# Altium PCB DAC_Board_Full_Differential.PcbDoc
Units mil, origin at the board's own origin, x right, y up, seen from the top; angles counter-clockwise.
Board outline 2155 x 3965 mil, 2 copper layers (Top Layer, Bottom Layer); 107 components, 72 nets, 303 pads, 34 vias.
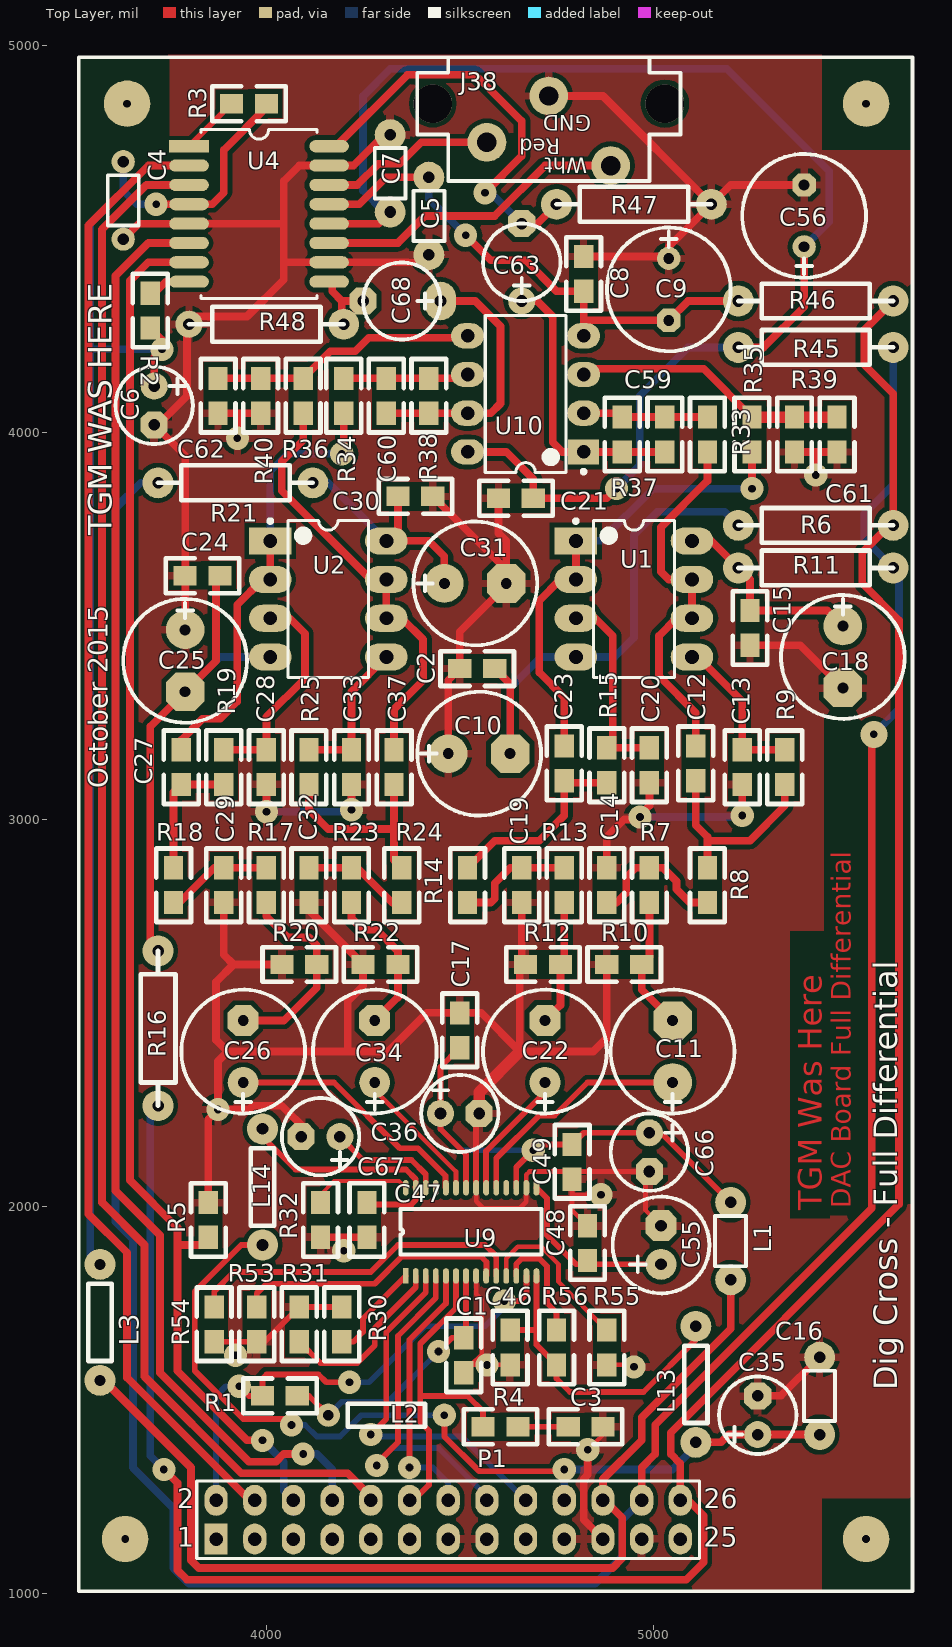
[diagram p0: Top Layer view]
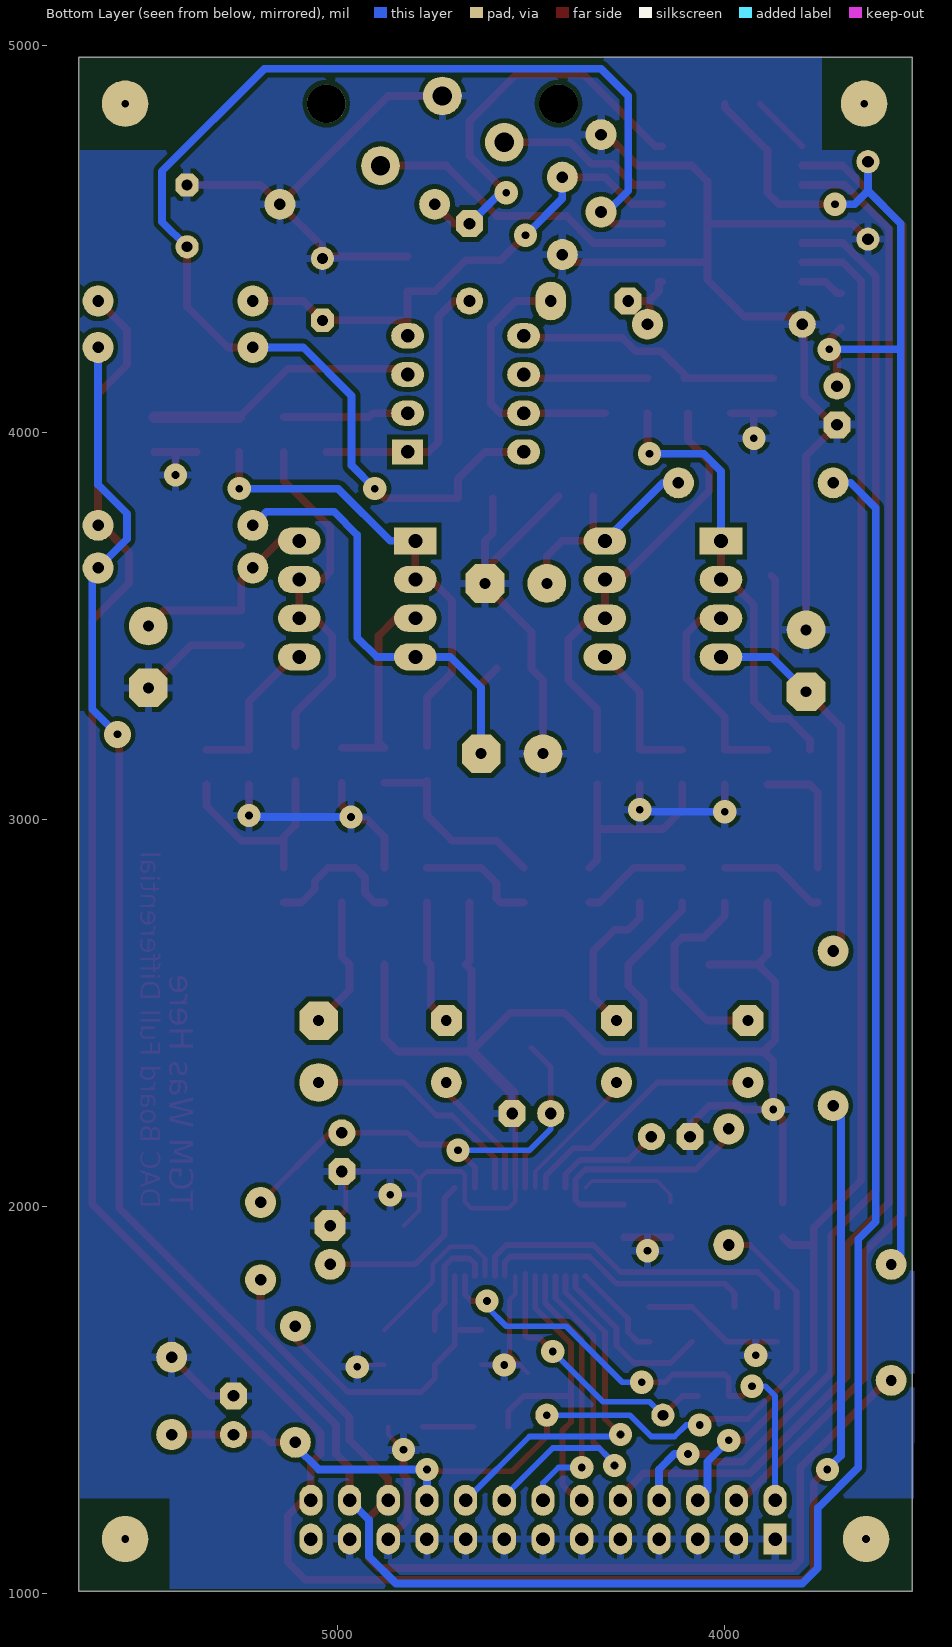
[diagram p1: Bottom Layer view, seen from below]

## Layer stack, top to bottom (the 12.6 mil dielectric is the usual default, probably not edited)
Top Layer: signal copper 1.4
Dielectric: core 12.6, FR-4, Dk 4.8
Bottom Layer: signal copper 1.4

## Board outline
3515,4970 5670,4970 5670,1005 3515,1005

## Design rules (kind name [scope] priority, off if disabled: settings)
Clearance Clearance_1 [(IsRegion)] p1: gap=12
Clearance [All] p2: gap=10
ComponentClearance [All] p1: gap=5 collisioncheckmode=3 verticalgap=10 showdistances=FALSE
HoleSize [All] p1: absolutevalues=TRUE maxlimit=255 minlimit=14 maxpercent=80.000 minpercent=20.000
MinimumSolderMaskSliver [All] p1: minsoldermaskwidth=5
PlaneConnect [All] p1: planeconnectstyle=Relief reliefexpansion=20 reliefentries=4 reliefconductorwidth=15 reliefairgap=10
PolygonConnect [All] p1: connectstyle=Relief reliefconductorwidth=20 reliefentries=4 polygonreliefangle="90 Angle"
RoutingVias [All] p1: holewidth=28 width=50 viastyle="Through Hole" minholewidth=28 minwidth=50 maxholewidth=28 maxwidth=50
SilkscreenOverComponentPads [All] p1: minsilkscreentomaskgap=10
SolderMaskExpansion [All] p1: expansion=4
Width [All] p1: maxlimit=255 minlimit=10 preferedwidth=10 minimp=50.000000 maximp=50.000000 favimp=50.000000
23 further rules are at their usual default settings.

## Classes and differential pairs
component class DAC_Board_Full_Differential: C2 C4 C5 C6 C7 C8 C9 C10 C11 C12 C13 C14 C15 C18 C19 C20 C21 C22 C23 C24 C25 C26 C27 C28 C29 C30 C31 C32 C33 C34 C37 C56 C59 C60 C61 C62 C63 C68 J38 L3 R2 R3 R5 R6 R7 R8 R9 R10 R11 R12 R13 R14 R15 R16 R17 R18 R19 R20 R21 R22 R23 R24 R25 R33 R34 R35 R36 R37 R38 R39 R40 R45 R46 R47 R48 R? U1 U2 U4 U10
component class DAC_Board_Full_Differential_Outputs: C1 C3 C16 C17 C35 C36 C46 C47 C48 C49 C55 C66 C67 L1 L2 L13 L14 P1 R1 R4 R30 R31 R32 R53 R54 R55 R56 U9

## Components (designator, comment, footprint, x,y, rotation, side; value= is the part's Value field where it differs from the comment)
C1 "100n" 0805 4510,1660 r270 top
C2 "100n" 0805 4590,3390 r180 top
C3 "27pF" 0805 4780,1430 r0 top
C4 "100n" AXIAL0.2#1 3630,4700 r270 top
C5 "100n" AXIAL0.2#2 4420,4660 r270 top
C6 "1uF" RB.1/.2 3710,4020 r90 top
C7 "100n" AXIAL0.2#2 4320,4570 r90 top
C8 "100n" 0805 4820,4455 r270 top
C9 "100uF" RB.16/.32-PTH#1 5040,4290 r90 top
C10 "100uF" RB.16/.32-PTH#2 4630,3170 r180 top
C11 "100uF" RB.16/.32-PTH#2 5050,2480 r270 top
C12 "1n8" 0805 5110,3190 r270 top
C13 "2n2" 0805 5230,3090 r90 top
C14 "15n" 0805 4880,2875 r270 top
C15 "100n" 0805 5250,3540 r270 top
C16 "100n" AXIAL0.2-PTH 5430,1410 r90 top
C17 "100n" 0805 4500,2410 r90 top
C18 "100uF" RB.16/.32-PTH#2 5490,3340 r90 top
C19 "15n" 0805 4660,2875 r270 top
C20 "2n2" 0805 4990,3095 r90 top
C21 "100n" 0805 4690,3830 r180 top
C22 "100uF" RB.16/.32-PTH#3 4720,2480 r270 top
C23 "1n8" 0805 4770,3190 r270 top
C24 "100n" 0805 3880,3630 r180 top
C25 "100uF" RB.16/.32-PTH#2 3790,3330 r90 top
C26 "100uF" RB.16/.32-PTH#3 3940,2480 r270 top
C27 "1n8" 0805 3780,3180 r270 top
C28 "2n2" 0805 4000,3090 r90 top
C29 "15n" 0805 3890,2785 r90 top
C30 "100n" 0805 4340,3835 r0 top
C31 "100uF" RB.16/.32-PTH#2 4620,3610 r180 top
C32 "15n" 0805 4110,2875 r270 top
C33 "2n2" 0805 4220,3090 r90 top
C34 "100uF" RB.16/.32-PTH#3 4280,2480 r270 top
C35 "10u" RB.1/.2 5270,1510 r270 top
C36 "10u" RB.1/.2 4550,2240 r180 top
C37 "1n8" 0805 4330,3180 r270 top
C46 "100n" 0805 4630,1680 r270 top
C47 "100n" 0805 4260,1920 r90 top
C48 "100n" 0805 4830,1950 r270 top
C49 "100n" 0805 4790,2070 r90 top
C55 "100uF" RB.1/.25-pth 5020,1850 r270 top
C56 "100uF" RB.16/.32-PTH#1 5390,4640 r270 top
C59 "1n" 0805 5030,4040 r270 top
C60 "1n" 0805 4310,4140 r270 top
C61 "1n" 0805 5475,3950 r90 top
C62 "1n" 0805 3875,4050 r90 top
C63 "22uF" RB.2/.2#1 4660,4340 r270 top
C66 "33uF" RB.1/.2 4990,2090 r90 top
C67 "3u3" RB.1/.2 4090,2180 r0 top
C68 "22uF" RB.2/.2#2 4450,4340 r0 top
J38 "Output Band 1" RCA-PCB-2IP 4570,4750 r180 top
L1 "bead" AXIAL0.2-pth 5200,2010 r270 top
L2 "bead" AXIAL0.3-pth#1 4460,1460 r180 top
L3 "bead" AXIAL0.3-pth#2 3570,1550 r90 top
L13 "bead" AXIAL0.3-pth#3 5110,1690 r270 top
L14 "bead" AXIAL0.3-pth#3 3990,1900 r90 top
P1 "Header 13X2" HDR2X13 3870,1140 r0 top
R1 "10K" 0805 3990,1510 r0 top
R2 "1K" 0805 3700,4360 r270 top
R3 "10K" 0805 3910,4850 r0 top
R4 "100R" 0805 4560,1430 r0 top
R5 "100K" 0805 3850,2010 r270 top
R6 "10" AXIAL0.4-pth 5220,3760 r0 top
R7 "196" 0805 4990,2875 r270 top
R8 "681" 0805 5140,2875 r270 top
R9 "464" 0805 5340,3180 r270 top
R10 "100k" 0805 4880,2625 r0 top
R11 "10" AXIAL0.4-pth 5220,3650 r0 top
R12 "100k" 0805 4760,2625 r180 top
R13 "196" 0805 4770,2875 r270 top
R14 "681" 0805 4520,2875 r270 top
R15 "464" 0805 4880,3185 r270 top
R16 "10" AXIAL0.4-pth 3720,2660 r270 top
R17 "196" 0805 4000,2875 r270 top
R18 "681" 0805 3760,2875 r270 top
R19 "464" 0805 3890,3180 r270 top
R20 "100k" 0805 4040,2625 r0 top
R21 "10" AXIAL0.4-pth 4120,3870 r180 top
R22 "100k" 0805 4340,2625 r180 top
R23 "196" 0805 4220,2875 r270 top
R24 "681" 0805 4350,2875 r270 top
R25 "464" 0805 4110,3180 r270 top
R30 "1K" 0805 4195,1740 r270 top
R31 "1K" 0805 4085,1740 r270 top
R32 "1K" 0805 4140,1920 r90 top
R33 "620" 0805 5140,3950 r90 top
R34 "620" 0805 4200,4050 r90 top
R35 "620" 0805 5255,3950 r90 top
R36 "620" 0805 4095,4050 r90 top
R37 "560" 0805 4920,4040 r270 top
R38 "560" 0805 4420,4140 r270 top
R39 "560" 0805 5365,4040 r270 top
R40 "560" 0805 3985,4140 r270 top
R45 "10" AXIAL0.4-PTH#1 5220,4220 r0 top
R46 "10" AXIAL0.4-PTH#1 5220,4340 r0 top
R47 "10k" AXIAL0.4-PTH#1 5150,4590 r180 top
R48 "10k" AXIAL0.4-PTH#2 4200,4280 r180 top
R53 "10K" 0805 3975,1650 r90 top
R54 "10K" 0805 3865,1650 r90 top
R55 "10K" 0805 4880,1590 r90 top
R56 "10K" 0805 4750,1590 r90 top
U1 "LM4562" DIP-8#1 4950,3570 r0 top
U2 "LM4562" DIP-8#1 4160,3570 r0 top
U4 "PGA2320" SO16W 3800,4740 r0 top
U9 "CS4398" TSSOP28 4360,1820 r90 top
U10 "LM4562" DIP-8#2 4670,4100 r180 top

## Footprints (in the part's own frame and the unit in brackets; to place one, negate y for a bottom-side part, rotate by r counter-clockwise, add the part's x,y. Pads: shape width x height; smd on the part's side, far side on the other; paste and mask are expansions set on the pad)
0805 [mil]
  rect 60x50 smd: 1(0,0) 2(90,0)
  silkscreen extent -50,-45 140,45, body extent -56,-51 146,51, height 10
AXIAL0.2#1 [mil]
  round 60 hole 30: 1(0,0) 2(200,0)
  silkscreen extent 35,-40 165,40, body extent 30,-45 170,45, height 200
AXIAL0.2#2 [mil]
  round 80 hole 30: 1(0,0) 2(200,0)
  silkscreen extent 35,-40 165,40, body extent 30,-45 170,45, height 200
AXIAL0.2-PTH [mil]
  round 80 hole 30: 1(0,0) 2(200,0)
  silkscreen extent 35,-40 165,40, body extent 30,-45 170,45, height 200
AXIAL0.2-pth [mil]
  round 80 hole 30: 1(0,0) 2(200,0)
  silkscreen extent 35,-40 165,40, body extent 30,-45 170,45, height 200
AXIAL0.3-pth#1 [mil]
  round 60 hole 20: 1(0,0)
  round 60 hole 28: 2(300,0)
  silkscreen extent 50,-30 250,30
AXIAL0.3-pth#2 [mil]
  round 80 hole 28: 1(0,0) 2(300,0)
  silkscreen extent 50,-30 250,30
AXIAL0.3-pth#3 [mil]
  round 80 hole 30: 1(0,0) 2(300,0)
  silkscreen extent 50,-30 250,30
AXIAL0.4-pth [mil]
  round 80 hole 30: 1(0,0) 2(400,0)
  silkscreen extent 0,-45 400,45, body extent 60,-45 340,45
AXIAL0.4-PTH#1 [mil]
  round 80 hole 30: 1(0,0) 2(400,0)
  silkscreen extent 0,-45 400,45, body extent 60,-45 340,45
AXIAL0.4-PTH#2 [mil]
  round 80 hole 30: 1(0,0)
  round 70 hole 30: 2(400,0)
  silkscreen extent 0,-45 400,45, body extent 60,-45 340,45
DIP-8#1 [mil] "DIP; 8 Leads; Row Spacing 7.62 mm; Pitch 2.54 mm"
  rect 110x70 hole 36: 1(-150,150)
  oval 110x70 hole 36: 2(-150,50) 3(-150,-50) 4(-150,-150) 5(150,-150) 6(150,-50) 7(150,50) 8(150,150)
  silkscreen extent -155,-203 104,206, body extent -142,-203 142,203, height 200
DIP-8#2 [mil] "DIP; 8 Leads; Row Spacing 7.62 mm; Pitch 2.54 mm"
  rect 80x65 hole 35: 1(-150,150)
  oval 85x65 hole 35: 2(-150,50) 3(-150,-50) 4(-150,-150) 5(150,-150) 6(150,-50) 7(150,50) 8(150,150)
  silkscreen extent -155,-203 104,206, body extent -142,-203 142,203, height 200
HDR2X13 [mil] "Connector; Header; 13x2 Position"
  rect 60x80 hole 35: 1(0,0)
  oval 60x80 hole 35: 2(0,100) 3(100,0) 4(100,100) 5(200,0) 6(200,100) 7(300,0) 8(300,100) 9(400,0) 10(400,100) 11(500,0) 12(500,100) 13(600,0) 14(600,100) 15(700,0) 16(700,100) 17(800,0) 18(800,100) 19(900,0) 20(900,100) 21(1000,0) 22(1000,100) 23(1100,0) 24(1100,100) 25(1200,0) 26(1200,100)
  silkscreen extent -50,-50 1250,150
RB.1/.2 [mil]
  round 70 hole 30: 1(100,0)
  oct 70x70 hole 30: 2(0,0)
  silkscreen extent -50,-100 150,100, body extent -50,-100 150,100
RB.1/.25-pth [mil]
  round 80 hole 30: 1(0,0)
  oct 80x80 hole 30: 2(-100,0)
  silkscreen extent -175,-125 75,125, body extent -170,-127 80,124
RB.2/.2#1 [mil]
  round 70 hole 30: 1(0,0)
  oct 70x70 hole 30: 2(-200,0)
  silkscreen extent -200,-100 0,100
RB.2/.2#2 [mil]
  oval 80x100 hole 30: 1(0,0)
  oct 70x70 hole 30: 2(-200,0)
  silkscreen extent -200,-100 0,100
RB.16/.32-PTH#1 [mil]
  round 60 hole 28: 1(160,0)
  oct 60x60 hole 28: 2(0,0)
  silkscreen extent -80,-160 240,160, body extent -80,-160 240,160, height 540
RB.16/.32-PTH#2 [mil]
  round 100 hole 28: 1(160,0)
  oct 100x100 hole 28: 2(0,0)
  silkscreen extent -80,-160 240,160, body extent -80,-160 240,160, height 540
RB.16/.32-PTH#3 [mil]
  round 80 hole 28: 1(160,0)
  oct 80x80 hole 28: 2(0,0)
  silkscreen extent -80,-160 240,160, body extent -80,-160 240,160, height 540
RCA-PCB-2IP [mil]
  round 100 hole 100: 0(-460,-100) 0(140,-100)
  round 100 hole 50: 1(0,0) 2(-160,-120) 3(-320,60)
  silkscreen extent -500,-220 180,100
SO16W [mm]
  rect 2.6x0.8 smd: 1(0,0)
  oval 2.6x0.8 smd: 2(0,-1.27) 3(0,-2.54) 4(0,-3.81) 5(0,-5.08) 6(0,-6.35) 7(0,-7.62) 8(0,-8.89) 9(9.2,-8.89) 10(9.2,-7.62) 11(9.2,-6.35) 12(9.2,-5.08) 13(9.2,-3.81) 14(9.2,-2.54) 15(9.2,-1.27) 16(9.2,0)
  silkscreen extent 0.8,-10 8.4,1.11
TSSOP28 [mil]
  rect 40x15 smd: 1(0,0)
  oval 40x15 smd: 2(0,-26) 3(0,-52) 4(0,-78) 5(0,-104) 6(0,-130) 7(0,-156) 8(0,-182) 9(0,-208) 10(0,-234) 11(0,-260) 12(0,-286) 13(0,-312) 14(0,-338) 15(228,-338) 16(228,-312) 17(228,-286) 18(228,-260) 19(228,-234) 20(228,-208) 21(228,-182) 22(228,-156) 23(228,-130) 24(228,-104) 25(228,-78) 26(228,-52) 27(228,-26) 28(228,0)
  silkscreen extent 55,-351 173,13

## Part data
C1 C4 C5 C7 C46 C47 C48 C49: library part CAP
C2 C3 C8 C15 C16 C17 C21 C24 C30: library part CAP, "Capacitor"
C6 C9 C10 C11 C18 C22 C25 C26 C31 C34 C35 C36 C55 C56 C63 C66 C67 C68: library part CAPACITOR, "Capacitor"
C12 C23 C27 C37: library part CAP, "Element14 p/n 1709050"
C13 C20 C28 C33: library part CAP, "Element14 p/n 9406220"
C14 C19 C29 C32: library part CAP, "Element14 p/n 1907326"
C59 C60 C61 C62: library part CAP, "Element14 p/n 1828937RL"
J38: library part RCA-PCB-2IP
L1 L2 L3 L13 L14: library part INDUCTOR1
P1: "Header, 13-Pin, Dual row"
R1 R2 R3 R4 R6 R10 R11 R12 R16 R20 R21 R22 R30 R31 R32 R45 R46 R47 R48 R53 R54 R55 R56: library part RES2
R5: library part Res2, "Resistor"
R7 R13 R17 R23: library part RES2, "Element14 p/n 2141755"
R8 R14 R18 R24: library part RES2, "Element14 p/n 1469954"
R9 R15 R19 R25: library part RES2, "Element14 p/n 2141776"
R33 R34 R35 R36: library part RES2, "Element14 p/n 9333410RL"
R37 R38 R39 R40: library part RES2, "Element14 p/n 9333363"
U1 U2 U10: library part LF353M(8), "Fast Settling Dual Operational Amplifier"

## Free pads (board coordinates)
  round 120 hole 20: 0(3635,1140) 0(3640,4850) 0(5550,1140) 0(5550,4850)

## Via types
v1: diameter 60, hole 20, Top Layer to Bottom Layer, 33 vias
v2: diameter 70, hole 20, Top Layer to Bottom Layer, 1 vias

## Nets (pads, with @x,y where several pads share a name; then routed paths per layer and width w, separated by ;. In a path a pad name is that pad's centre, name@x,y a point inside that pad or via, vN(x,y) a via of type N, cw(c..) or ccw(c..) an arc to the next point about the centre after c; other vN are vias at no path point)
+9V_FILT: C7.1 C21.1 C56.1 R45.1 U4.12 U10.8 | length 3488.2
  Top Layer w20: U4.12 4290,4540 C7.1 ; U10.8 4620,3950 4690,3880 C21.1 4880,3830 v1(4905,3855) ; R45.1 5285,4220 5390,4325 C56.1
  Bottom Layer w20: C7.1 4305,4570 4250,4625 4250,4870 4320,4940 5190,4940 5455,4675 5455,4545 C56.1 ; v1(4905,3855) 4965,3915 4965,4095 5090,4220 R45.1
+9V_FILT_L: C30.1 C31.1 R21.1 U2.8 | length 616.1
  Top Layer w20: C30.1 4340,3750 U2.8 4420,3720 4460,3680 C31.1
  Bottom Layer w20: R21.1 4160,3870 U2.8
+9V_FILT_R: C15.1 C18.1 R11.1 U1.8 | length 528
  Top Layer w20: U1.8 5150,3720 5250,3620 C15.1 5450,3540 C18.1
-9V_FILT: C5.1 C8.2 C9.2 R46.1 U4.13 U10.4 | length 1401.9
  Top Layer w20: U4.13 4240,4590 4310,4660 C5.1 ; v1(4515,4510) 4580,4445 4670,4445 4750,4365 C8.2 U10.4 ; 4825,4290 C9.2 5090,4340 R46.1
  Bottom Layer w20: C5.1@4420,4690 4420,4605 v1(4515,4510)
-9V_FILT_L: C24.1 C25.2 R16.1 U2.4 | length 1310.1
  Top Layer w20: R16.1 3700,2680 3700,3240 C25.2 3870,3410 3870,3620 C24.1
  Bottom Layer w20: C25.2 3880,3420 U2.4
-9V_FILT_R: C2.1 C10.2 R6.1 U1.4 | length 1354.8
  Top Layer w20: C2.1 4630,3350 C10.2
  Bottom Layer w20: C10.2 4630,3340 4710,3420 U1.4 4900,3420 4950,3470 4950,3735 5010,3795 5185,3795 R6.1
AGND: C1.2 C2.2 C3.2 C4.2 C5.2 C6.2 C7.2 C8.1 C9.1 C10.1 C13.1 C14.1 C15.2 C16.2 C17.2 C18.2 C19.2 C20.1 C21.2 C24.2 C25.1 C28.1 C29.1 C30.2 C31.2 C32.2 C33.1 C35.2 C36.2 C46.2 C47.1 C48.1 C49.1 C55.2 C56.2 C61.1 C62.1 C66.2 C67.2 J38.2 P1.1 P1.3 P1.5 P1.7 P1.9 P1.11 P1.13 P1.15 P1.17 P1.19 P1.21 P1.23 R5.1 R10.1 R12.2 R20.1 R22.2 R30.1 R31.1 R32.1 R39.2 R40.2 R47.1 R48.2 R53.1 R54.1 R55.1 U4.5 U4.10 U4.15 U9.8 U9.16 U9.21 | length 12678.6
  Top Layer w12: v1@3920,1605 3920,1650 ; C1.2 C1.2@4530,1590 ; U9.8 4542,1773 4556.5,1758.5 4556.5,1616.5 C1.2@4530,1590 ; U9.21 4542,2013 4560,1995 4655,1995 4672,2012 U9.16 4672,2082 4680,2090 4770,2090 C49.1 ; C36.2@4542,2232 C36.2 ; C46.2 C1.2@4530,1590 ; 4790,2030 v1(4865,2030) ; C48.1 4790,1990 C49.1 ; v1@4831.19,1365 4830.89,1365 4825,1365 v1(4830.89,1370.89) 4870,1410 C3.2 ; R55.1 4945,1590 v1(4950,1585) ; C55.2 4980,1990 4980,2080 C66.2 4810,2090 C49.1
  Top Layer w15: R54.1 3995,1650 R31.1 R30.1 ; U9.21 C36.2@4542,2232
  Top Layer w20: C4.2 3670,4540 U4.5 4045,4540 ; C25.1 C24.2 3790,3940 3715,4015 3795,4095 3795,4275 3820,4300 3950,4300 4045,4395 4045,4440 ; R5.1 3850,2225 v1(3875,2250) ; C62.1 3925,4050 ; C29.1 3890,2650 3915,2625 ; v1(3925,3985) 3925,4050 ; R40.2 3925,4050 ; v1(4000,3020) C28.1 ; R20.1 3915,2625 ; C67.2@4105,2195 4040,2260 3965.15,2260 3955.15,2250 v1(3875,2250) ; C32.2 4110,2765 R22.2 4250,2570 4210,2530 4210,2400 ; R32.1 C47.1 ; 4190,1920 4190,1875 4195,1880 4195,1885 v1(4200,1885) ; v1(4220,3025) C33.1 ; C7.2 4305,4770 4225,4690 U4.15 4085,4690 4045,4650 4045,4540 ; C5.2 4400,4440 U4.10 4045,4440 ; C30.2 4620,3645 C31.2 ; C10.1 4470,3360 C2.2 4500,3485 4620,3605 C31.2 ; C21.2 4600,3740 4620,3720 C31.2 ; C19.2 4660,2635 R12.2 4655,2610 4655,2400 ; J38.2 4870,4870 R47.1 ; C8.1 5035,4455 C9.1 5040,4480 R47.1 ; v1(4830.89,1370.89) 4830.89,1365 4830.89,1305.89 4820,1295 4820,1190 P1.21 ; R10.1 4880,2435 4845,2400 4655,2400 ; C14.1 4880,2955 4925,3000 4955,3000 4990,3035 C20.1 ; v1(5230,3010) C13.1 ; C15.2 5380,3450 C18.2 ; C35.2 5330,1510 C16.2 ; R39.2 5420,3950 ; C56.2 5200,4640 R47.1 ; v1(5420,3890) 5420,3950 ; C61.1 5420,3950 ; v1(3875,2250) 3875,2375 3900,2400 ; 3900,2400 3870,2430 3870,2580 3915,2625 ; 3900,2400 4210,2400 ; 4045,4440 4045,4540 ; 4210,2400 4315,2400 4415,2500 C17.2 4555,2500 4655,2400
  Top Layer w30: C36.2 4550,2295 4655,2400
  Bottom Layer w20: v1(4000,3020) v1@4215,3020 ; v1(4965.99,3005.99) v1@5225.99,3005.99
  other v1: 4570,1590 3920,1615
AOUTL+: C34.1 U9.23 | length 359
  Top Layer w12: C34.1 4280,2300 4490,2090 U9.23
AOUTL-: C26.1 U9.24 | length 654.1
  Top Layer w15: C26.1 4175,2320 4345,2150 4391.77,2150 4463,2078.77 4463,2049 U9.24
AOUTR+: C22.1 U9.20 | length 335
  Top Layer w15: U9.20 4568,2143 4720,2295 C22.1
AOUTR-: C11.1 U9.19 | length 613.2
  Top Layer w15: U9.19 4594,2124 4705,2235 4745,2235 4830,2320 C11.1
CCLK: P1.8 U4.6 | length 3753
  Top Layer w20: U4.6 3695,4490 3610,4405 3610,2040 3725,1925 3725,1570 3955,1340 4025,1340 4045,1360 v1(4095,1360)
  Bottom Layer w20: v1(4095,1360) 4130,1360 4170,1320 P1.8
CDIN: P1.10 U4.3 | length 4006.6
  Top Layer w20: U4.3 3690,4640 3575,4525 3575,2010 3685,1900 3685,1560 3935,1310 4210,1310 4270,1250 P1.10
CDOUT: P1.6 R5.2 U4.7 | length 3641.4
  Top Layer w20: 3770,1900 3830,1900 R5.2 ; U4.7 3695,4440 3647.5,4392.5 3647.5,2067.5 3770,1945 3770,1575 3950,1395 v1(3990,1395)
  Bottom Layer w20: v1(3990,1395) 4045,1340 4045,1265 P1.6 P1.6@4070,1210
CS_L: P1.4 U4.2 | length 3804.8
  Top Layer w20: U4.2 3695,4690 3540,4535 3540,1980 3640,1880 3640,1557.18 3957.18,1240 P1.4
DAC_OUTPUT_L: C68.2 R48.1 U4.9 | length 206.4
  Top Layer w20: U4.9 4170,4390 4170,4365 4195,4340 ; R48.1@4195,4285 4195,4340 ; C68.2@4230,4320 C68.2 4195,4340
DAC_OUTPUT_R: C63.2 R47.2 U4.16 | length 1087.3
  Top Layer w20: U4.16 4180,4740 4365,4925 4540,4925 4660,4805 4660,4715 v1(4565,4620) ; C63.2 4700,4540 R47.2
  Bottom Layer w20: v1(4565,4620) 4580,4620 C63.2
DVDD_3.3: C16.1 C35.1 L2.1 L13.2 L14.1 P1.20 | length 2353.3
  Top Layer w15: L14.1 3935,1900 3815,1780 3815,1575 3940,1450 4050,1450 v1(4065,1435) ; L2.1 4460,1405 4550,1315 v1@4770,1315
  Top Layer w20: L13.2 5175,1390 5195,1410 C35.1 C16.1
  Bottom Layer w15: v1(4065,1435) 4100,1435 4130,1405 4190,1405 4245,1460 L2.1
  Bottom Layer w20: P1.20 v1(4770,1320) 5050,1320 5110,1380 L13.2
LEFT+: C37.1 R36.1 U2.6 U2.7 | length 1121.9
  Top Layer w20: R36.1 4095,3980 4040,3925 4040,3850 4270,3620 U2.7 U2.6 4350,3520 4405,3465 4405,3360 4330,3285 C37.1
LEFT-: C27.1 R34.1 U2.1 U2.2 | length 1164.1
  Top Layer w20: C27.1 3780,3205 3835,3260 3880,3260 3925,3305 3925,3555 3990,3620 U2.2 U2.1 ; v1(4195,3945) 4200,3950 R34.1
  Bottom Layer w20: U2.1 4010,3900 4055,3945 v1(4195,3945)
LRCK: P1.14 U9.5 | length 731.7
  Top Layer w15: v1@4370,1310 4370,1655.1 4464,1749.1 U9.5
  Bottom Layer w15: v1(4370,1325) 4370,1310 4385,1325 4430,1325 4470,1285 P1.14
MCLK: P1.12 R4.1 U9.6 | length 865.8
  Top Layer w15: P1.12 4380,1240 4420,1280 4420,1420 4397.5,1442.5 4397.5,1644.68 4490,1737.18 U9.6 ; 4405,1510 4520,1510 4560,1470 R4.1
MUTE_L: P1.25
NetC1_1: C1.1 L2.2 R1.2 U9.7 | length 711
  Top Layer w15: R1.2@4070,1510 4110,1510 L2.2 ; v1(4445,1625) 4480,1660 C1.1 4516,1666 U9.7 U9.7@4516,1825
  Bottom Layer w15: L2.2 4195,1495 4315,1495 v1(4445,1625)
NetC3_1: C3.1 R4.2 | length 130
  Top Layer w15: R4.2 C3.1
NetC4_1: C4.1 C6.1 L3.2 R2.2 R3.2 U4.4 | length 3785.5
  Top Layer w20: R2.2 3730,4240 v1(3730,4215) ; C6.1 v1@3710,4195 ; v1(3715,4590) U4.4 3860,4590 3890,4620 3890,4730 4000,4840 R3.2
  Bottom Layer w20: L3.2 3545,1875 3545,4215 ; C4.1 3630,4625 ; v1(3715,4590) 3665,4590 3630,4625 ; v1(3730,4215) 3545,4215 ; 3545,4215 3545,4540 3630,4625
NetC11_2: C11.2 R7.2 R10.2 | length 346.4
  Top Layer w20: R7.2 4990,2645 R10.2 4970,2560 C11.2
NetC12_2: C12.2 R8.1 R9.2 | length 529.7
  Top Layer w20: C12.2 5110,2985 5140,2955 R8.1 ; 5140,2945 5250,2945 5340,3035 R9.2
NetC13_2: C13.2 R9.1 U1.5 | length 412.6
  Top Layer w20: U1.5 5115,3420 5230,3305 C13.2 R9.1
NetC14_2: C14.2 R7.1 R8.2 | length 369.7
  Top Layer w20: C14.2 4905,2785 4930,2810 4930,2850 4955,2875 R7.1 5025,2875 5060,2840 5060,2820 5095,2785 R8.2
NetC19_1: C19.1 R13.1 R14.2 | length 310.7
  Top Layer w20: R14.2 4580,2785 4590,2795 4590,2835 4630,2875 C19.1 R13.1
NetC20_2: C20.2 R15.1 U1.3 | length 519.9
  Top Layer w20: U1.3 4850,3520 4895,3475 4895,3200 R15.1 C20.2
NetC22_2: C22.2 R12.1 R13.2 | length 325.7
  Top Layer w20: C22.2 4760,2520 R12.1 4770,2635 R13.2
NetC23_2: C23.2 R14.1 R15.2 | length 508
  Top Layer w20: R14.1 4590,2945 4705,2945 4770,3010 C23.2 4775,3095 R15.2
NetC26_2: C26.2 R17.2 R20.2 | length 531.3
  Top Layer w20: C26.2 4045,2480 4130,2565 R20.2 4130,2675 4110,2695 4055,2695 4000,2750 R17.2
NetC27_2: C27.2 R18.1 R19.2 | length 333.3
  Top Layer w20: R18.1 3760,3070 C27.2 R19.2
NetC28_2: C28.2 R19.1 U2.3 | length 558
  Top Layer w20: R19.1 C28.2 4000,3265 4100,3365 4100,3480 4060,3520 U2.3
NetC29_2: C29.2 R17.1 R18.2 | length 277.3
  Top Layer w20: R18.2 3775,2785 3865,2875 C29.2 R17.1
NetC32_1: C32.1 R23.1 R24.2 | length 277.3
  Top Layer w20: C32.1 R23.1 4235,2875 4325,2785 R24.2
NetC33_2: C33.2 R25.1 U2.5 | length 387.3
  Top Layer w20: R25.1 C33.2 4220,3330 U2.5
NetC34_2: C34.2 R22.1 R23.2 | length 400.1
  Top Layer w20: R23.2 4220,2745 4250,2715 4285,2715 4340,2660 R22.1 4340,2540 C34.2
NetC37_2: C37.2 R24.1 R25.2 | length 529
  Top Layer w20: R25.2 4110,3025 4160,2975 4330,2975 ; C37.2 4330,2895 R24.1
NetC46_1: C46.1 L13.1 R56.1 U9.14 | length 820
  Top Layer w15: C46.1 4698,1680 ; U9.14 4698,1642 R56.1 4750,1555 4785,1520 4975,1520 5110,1655 L13.1
NetC47_2: C47.2 L14.2 U9.27 | length 647.4
  Top Layer w15: L14.2 3990,2180 4075,2095 4360.86,2095 4386,2069.86 U9.27 ; C47.2@4260,2005 4375,2005 4386,2016 U9.27 ; U9.27@4385,2049 U9.27
NetC48_2: C48.2 C55.1 U9.15 | length 460.2
  Top Layer w15: U9.15 4725,2021 4725,1925 4800,1850 C55.1
NetC59_1: C59.1 R33.2 R37.1 U10.2 | length 324.1
  Top Layer w20: U10.2 4910,4050 R37.1 C59.1 R33.2
NetC59_2: C59.2 C63.1 R37.2 U10.1 | length 721.9
  Top Layer w20: C63.1 4700,4340 4740,4300 4740,3975 4765,3950 U10.1 R37.2 C59.2
NetC60_1: C60.1 R34.2 R38.1 U10.6 | length 324.1
  Top Layer w20: R34.2 C60.1 R38.1 4510,4140 U10.6
NetC60_2: C60.2 C68.1 R38.2 U10.7 | length 687.3
  Top Layer w20: C60.2 R38.2 U10.7 4580,4050 4605,4075 4605,4275 4540,4340 C68.1
NetC61_2: C61.2 R35.2 R39.1 U10.3 | length 713
  Top Layer w20: U10.3 4835,4165 5130,4165 R35.2
  Top Layer w30: R35.2 R39.1 C61.2
NetC62_2: C62.2 R36.2 R40.1 U10.5 | length 694.7
  Top Layer w20: C62.2 R40.1 R36.2 ; R36.2@4105,4140 R36.2 ; U10.5@4510,4260 4495,4245 4265,4245 4230,4210 4165,4210 R36.2
NetC67_1: C67.1 U9.26 | length 297.2
  Top Layer w15: C67.1 4250,2120 4375,2120 4412,2083 U9.26
NetJ38_1: J38.1 U4.14 | length 453.4
  Top Layer w20: U4.14 4235,4640 4290,4695 4345,4695 4400,4750 J38.1
NetJ38_3: J38.3 U4.11 | length 810.6
  Top Layer w20: U4.11 4340,4490 4410,4560 4590,4560 4720,4690 J38.3
NetL1_2: L1.2 L3.1 P1.22 | length 2579.2
  Top Layer w20: L3.1@3575,1555 3805,1325 3805,1085 3825,1065 4895,1065 4920,1090 4920,1195 4875,1240 P1.22 4870,1295 4970,1395 4970,1453.98 5200,1683.98 L1.2
NetP1_24: P1.24 R11.2 R21.2 R45.2 | length 7634.1
  Top Layer w20: P1.24 4970,1325 5005,1360 5005,1435 5565,1995 5565,3215 v2(5570,3220)
  Bottom Layer w20: R21.2 3675,3870 3610,3805 3610,1960 3655,1915 3655,1325 3760,1220 3760,1065 3800,1025 4850,1025 4920,1095 4920,1190 P1.24 ; v2(5570,3220) 5635,3285 5635,3635 5545,3725 5545,3790 5620,3865 R45.2
NetP1_26: P1.26 R6.2 R16.2 R46.2 | length 6332.2
  Top Layer w20: v1(3735,1320) 3770,1285 3770,1060 3795,1035 5085,1035 5130,1080 5130,1200 5090,1240 P1.26 5070,1335 5045,1360 5045,1415 5635,2005 5635,3515 5540,3610 5540,3690 5620,3770 5620,4100 5545,4175 5545,4265 R46.2
  Bottom Layer w20: R16.2@3700,2260 3715,2245 3695,2245 3700,2240 3700,1355 v1(3735,1320)
NetR2_1: R2.1 U4.8 | length 112.4
  Top Layer w20: R2.1 3710,4360 3740,4390 U4.8
NetR3_1: R3.1 U4.1 | length 155.6
  Top Layer w15: U4.1 R3.1
NetR30_2: R30.2 U9.1 | length 255.9
  Top Layer w15: R30.2 4225,1650 4250,1675 4250,1710 U9.1
NetR31_2: R31.2 U9.2 | length 460.3
  Top Layer w15: R31.2 4140,1595 4235,1595 4280,1640 4280,1685 4386,1791 U9.2
NetR32_2: R32.2 U9.28 | length 261.5
  Top Layer w10: R32.2 4140,2030 4175,2065 4343,2065 U9.28
NetR53_2: R53.2 U9.9 | length 709.1
  Top Layer w15: R53.2 3975,1775 4000,1800 4280,1800 4350,1870 4555,1870 4569,1856 U9.9@4569,1821
NetR54_2: R54.2 U9.10 | length 881.7
  Top Layer w15: R54.2 3865,1780 3915,1830 4270,1830 4340,1900 4565,1900 4594,1871 U9.10
NetR55_2: R55.2 U9.11 | length 432.8
  Top Layer w12: U9.11 4620,1865 4650,1895 4710,1895 4755,1850 4755,1805 R55.2
NetR56_2: R56.2 U9.12 | length 299.4
  Top Layer w15: U9.12 4646,1851 4660,1865 4705,1865 4725,1845 4725,1750 4750,1725 R56.2
RIGHT+: C23.1 R35.1 U1.1 U1.2 | length 1240.6
  Top Layer w20: C23.1 4770,3315 4705,3380 4705,3565 4760,3620 U1.2 U1.1 ; v1(5255,3855) R35.1 R35.1@5255,3935
  Bottom Layer w20: U1.1 4865,3720 5000,3855 v1(5255,3855)
RIGHT-: C12.1 R33.1 U1.6 U1.7 | length 976
  Top Layer w20: C12.1 5110,3275 5015,3370 5015,3475 5060,3520 U1.6 U1.7 5040,3620 5020,3640 5020,3755 5140,3875 R33.1
RST_L: P1.2 R1.1 U9.13 | length 1301
  Top Layer w15: v1(3930,1535) 3955,1510 R1.1 3990,1555 4000,1565 4135,1565 4155,1545 v1(4215,1545) ; v1(4615,1755) 4655,1755 4672,1772 U9.13
  Bottom Layer w15: P1.2 3870,1510 3895,1535 v1(3930,1535) ; v1(4215,1545) 4265,1545 4410,1690 4565,1690 4615,1740 v1(4615,1755)
SCLK: P1.16 U9.4 | length 927.6
  Top Layer w15: v1(4285,1330) 4290,1330 4300,1340 4300,1350 4340,1390 4340,1665 4438,1763 U9.4
  Bottom Layer w15: v1(4285,1330) 4290,1330 4300,1340 4300,1350 4325,1375 4445,1375 4570,1250 P1.16
SDIN_1: P1.18 U9.3 | length 949.2
  Top Layer w15: v1(4270,1410) 4310,1450 4310,1675 4412,1777 U9.3
  Bottom Layer w15: v1(4270,1410) 4265,1405 4505,1405 P1.18
VA: C17.1 C36.1 C49.2 C66.1 L1.1 U9.17 U9.22 | length 1431.3
  Top Layer w15: C17.1 4450,2360 C36.1 4450,2200 4516,2134 U9.22 ; U9.17 4646,2101 4705,2160 C49.2 4820,2190 C66.1 5020,2190 L1.1
  Bottom Layer w15: C36.1 4450,2200 4505,2145 v1(4690,2145)
pads on no net: J38.0 U9.18 U9.25

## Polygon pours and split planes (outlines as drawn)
AGND on Top Layer "GND" (solid, remove dead copper, pour order 1000): 5666.05,4976.33 3511.05,4976.33 3508.55,4973.83 3508.55,1008.83 5663.55,1008.83 5668.55,1003.83
AGND on Bottom Layer "GND" (solid, remove dead copper, pour order 1001): 3506.46,4971.02 5666.46,4971.02 5666.46,1016.02 5661.46,1011.02 3516.46,1011.02 3511.46,1006.02

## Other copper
Top Layer:
  pour cut-out: 5675,1240 5670,1245 5435,1245 5435,1000 5675,1000
  pour cut-out: 3750,1240 3745,1245 3510,1245 3510,1000 3750,1000
  pour cut-out: 3750,4970 3745,4975 3510,4975 3510,4730 3750,4730
  pour cut-out: 5675,4970 5670,4975 5435,4975 5435,4730 5675,4730
  text "DAC Board Full Differential" at 5510,1995 h50 r90
  text "TGM Was Here" at 5435,1990 h60 r90
Bottom Layer:
  pour cut-out: 5675,4970 5670,4975 5435,4975 5435,4730 5675,4730
  pour cut-out: 3750,4970 3745,4975 3510,4975 3510,4730 3750,4730
  pour cut-out: 3750,1240 3745,1245 3510,1245 3510,1000 3750,1000
  pour cut-out: 5675,1240 5670,1245 5435,1245 5435,1000 5675,1000

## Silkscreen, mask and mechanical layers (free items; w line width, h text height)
Top Overlay:
  the board outline again, w10
  text "TGM WAS HERE" at 3600,3735 h60 r90
  text "October 2015" at 3590,3080 h50 r90
  text "Dig Cross - Full Differential" at 5630,1525 h60 r90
